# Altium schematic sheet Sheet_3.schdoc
size 305 x 189 mm
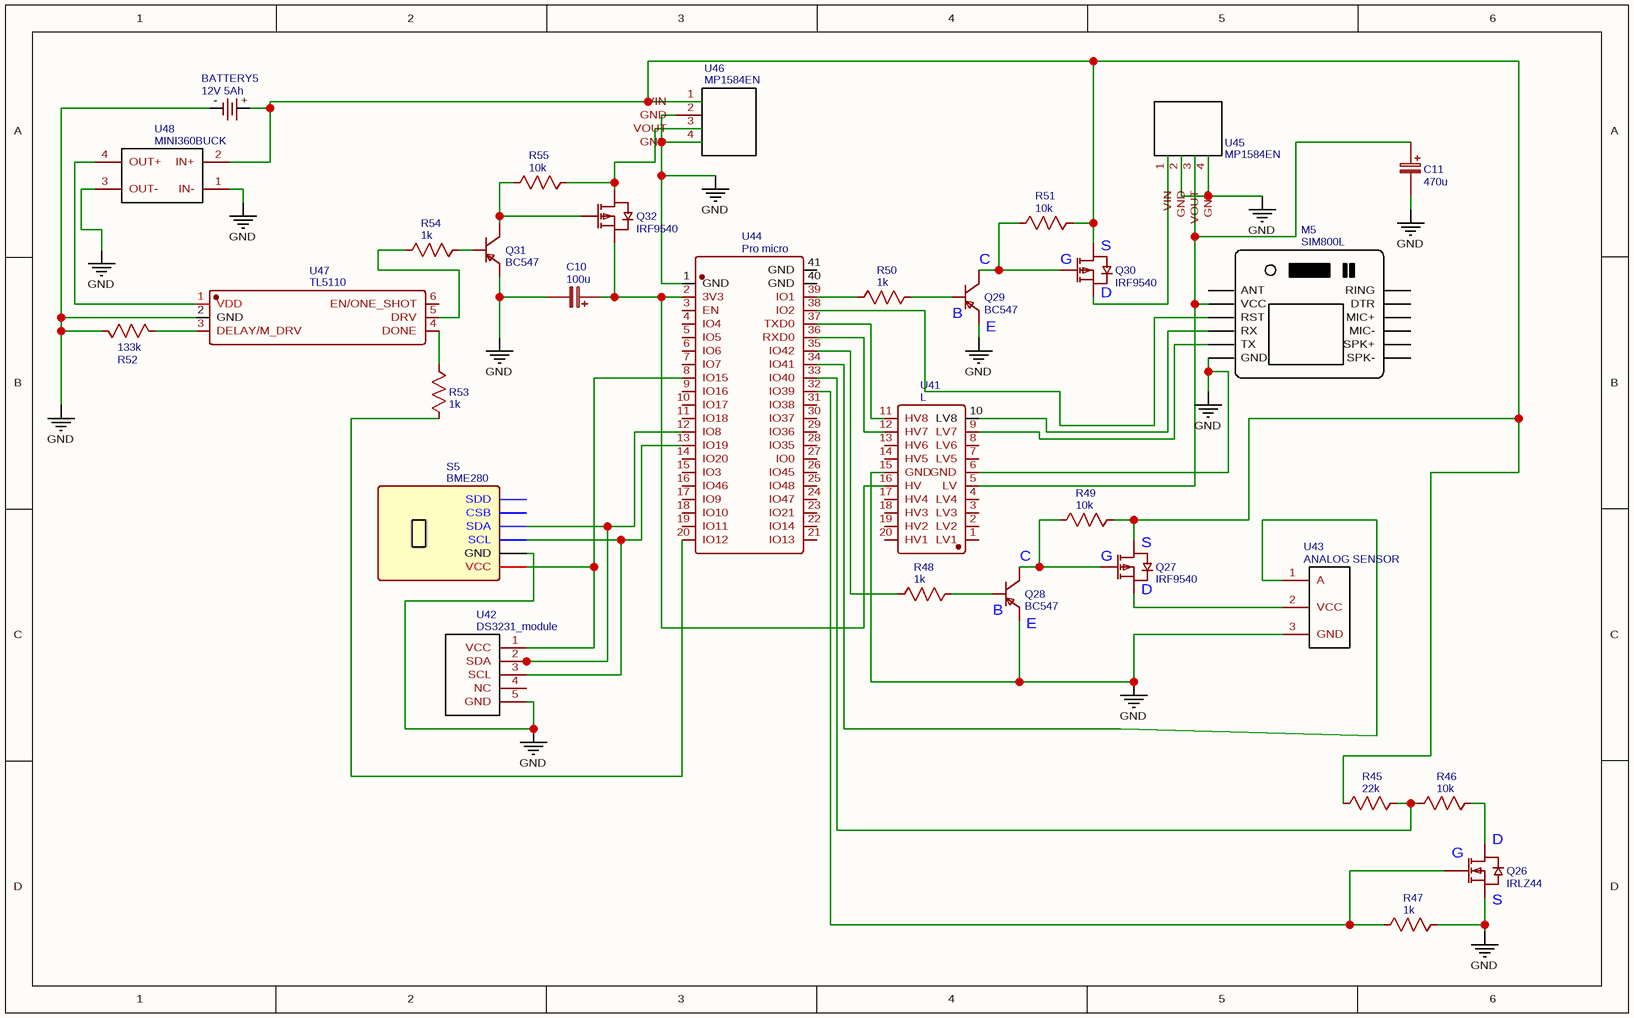
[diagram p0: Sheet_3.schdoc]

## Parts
BATTERY5  12V 5Ah  [BATTERY-SMD-MY-2032]
C10  100u  [CASE-A_3216]
C11  470u  [CASE-A_3216]
M5  SIM800L  [SIM800LMODULE_SIM800LMODULE]
Q26  IRLZ44  [TO-220-3_L10.0-W4.5-P2.54-T]
Q27  IRF9540  [TO-263-2_L10.0-W9.1-P5.08-LS15.2-BR]
Q28  BC547  [SOT-23-3_L2.9-W1.6-P1.90-LS2.8-TR-CW]
Q29  BC547  [SOT-23-3_L2.9-W1.6-P1.90-LS2.8-TR-CW]
Q30  IRF9540  [TO-263-2_L10.0-W9.1-P5.08-LS15.2-BR]
Q31  BC547  [SOT-23-3_L2.9-W1.6-P1.90-LS2.8-TR-CW]
Q32  IRF9540  [TO-263-2_L10.0-W9.1-P5.08-LS15.2-BR]
R45  22k  [R0603]
R46  10k  [R0603]
R47  1k  [R0603]
R48  1k  [R0603]
R49  10k  [R0603]
R50  1k  [R0603]
R51  10k  [R0603]
R52  133k  [R0603]
R53  1k  [R0603]
R54  1k  [R0603]
R55  10k  [R0603]
S5  BME280  [BME280]
U41  L  [MPN-TH-20_L28.0-W14.0-P2.54-BL]
U42  DS3231_module  [DS3231]
U43  ANALOG SENSOR  [ANALOG SENSOR V1]
U44  Pro micro  [WIRELM-SMD_ESP32-S3-WROOM-1U]
U45  MP1584EN  [MP1584EN]
U46  MP1584EN  [MP1584EN]
U47  TL5110  [TSOT-23-6_L2.9-W1.6-P0.95-LS2.8-BR]
U48  MINI360BUCK  [MINI360BUCK]

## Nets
GND: BATTERY5.-(BAT-) C10.2 C11.2 M5.6(GND) Q26.3(S) Q28.1(E) Q29.1(E) Q31.1(E) R47.2 R52.1 S5.2(GND) U41.6(GND) U41.15(GND) U42.5(GND) U43.3(GND) U44.1(GND) U45.2(GND) U45.4(GND) U46.4(GND) U47.2(GND) U48.1(IN-) U48.3(OUT-)
NetBATTERY5_+: BATTERY5.+(BAT+) Q27.4(D) Q30.4(D) R45.1 R49.1 R51.1 U46.1(VIN) U48.2(IN+)
NetC10_1: C10.1 Q32.3(S) U41.16(HV) U44.2(3V3)
NetC11_1: C11.1 M5.2(VCC) U41.5(LV) U45.3(VOUT)
NetM5_3: M5.3(RST) U44.38(IO2)
NetM5_4: M5.4(RX) U41.10(LV8)
NetM5_5: M5.5(TX) U41.9(LV7)
NetQ26_1: Q26.1(G) R47.1 U44.32(IO39)
NetQ26_2: Q26.2(D) R46.2
NetQ27_1: Q27.1(G) Q28.3(C) R49.2
NetQ27_3: Q27.3(S) U43.2(VCC)
NetQ28_2: Q28.2(B) R48.2
NetQ29_2: Q29.2(B) R50.2
NetQ29_3: Q29.3(C) Q30.1(G) R51.2
NetQ30_3: Q30.3(S) U45.1(VIN)
NetQ31_2: Q31.2(B) R54.1
NetQ31_3: Q31.3(C) Q32.1(G) R55.2
NetQ32_4: Q32.4(D) R55.1 U46.3(VOUT)
NetR45_2: R45.2 R46.1 U44.33(IO40)
NetR48_1: R48.1 U44.35(IO42)
NetR50_1: R50.1 U44.39(IO1)
NetR52_2: R52.2 U47.3(DELAY/M_DRV)
NetR53_1: R53.1 U47.4(DONE)
NetR53_2: R53.2 U44.20(IO12)
NetR54_2: R54.2 U47.5(DRV)
NetS5_1: S5.1(VCC) U42.1(VCC) U44.8(IO15)
NetS5_3: S5.3(SCL) U42.3(SCL) U44.13(IO19)
NetS5_4: S5.4(SDA) U42.2(SDA) U44.12(IO8)
NetU41_11: U41.11(HV8) U44.37(TXD0)
NetU41_12: U41.12(HV7) U44.36(RXD0)
NetU43_1: U43.1(A) U44.34(IO41)
NetU47_1: U47.1(VDD) U48.4(OUT+)

Not connected (* = marked no-connect by the designer): M5 1(ANT) 7(SPK-) 8(SPK+) 9(MIC-) 10(MIC+) 11(DTR) 12(RING); S5 5(CSB) 6(SDD); U41 1(LV1) 2(LV2) 3(LV3) 4(LV4) 7(LV5) 8(LV6) 13(HV6) 14(HV5) 17(HV4) 18(HV3) 19(HV2) 20(HV1); U42 4(NC); U44 3(EN) 4(IO4) 5(IO5) 6(IO6) 7(IO7) 9(IO16) 10(IO17) 11(IO18) 14(IO20) 15(IO3) 16(IO46) 17(IO9) 18(IO10) 19(IO11) 21(IO13) 22(IO14) 23(IO21) 24(IO47) 25(IO48) 26(IO45) 27(IO0) 28(IO35) 29(IO36) 30(IO37) 31(IO38) 40(GND) 41(GND); U46 2(GND); U47 6(EN/ONE_SHOT)

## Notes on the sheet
- (near Q29) C
- (near Q30) G
- (near Q30) S
- (near Q30) D
- (near Q29) B
- (near Q29) E
- (near Q28) C
- (near Q27) G
- (near Q27) S
- (near Q28) B
- (near Q28) E
- (near Q27) D
- (near Q26) G
- (near Q26) S
- (near Q26) D

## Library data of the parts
BATTERY5 = 12V 5Ah: Manufacturer: MYOUNG(美阳); Manufacturer Part: MY-2032-10; Contributor: lcsc
C10 = 100u: nameAlias: Value(F); Contributor: LCEDA_Lib
C11 = 470u: nameAlias: Value(F); Contributor: LCEDA_Lib
M5 = SIM800L: Contributor: sharad.rask
Q26 = IRLZ44: Manufacturer: Infineon(英飞凌); Manufacturer Part: IRLZ44NPBF
Q27 Q30 Q32 = IRF9540: Manufacturer: IR; Manufacturer Part: IRF5210STRLPBF; Paste Type: expand; Contributor: LCEDA_Lib
Q28 Q29 Q31 = BC547: Manufacturer: KEC; Manufacturer Part: 2N3906S-RTK/PS; Contributor: LCEDA_Lib
R45 = 22k: nameAlias: Value(Ω); Contributor: LCEDA_Lib
R46 R49 R51 R55 = 10k: nameAlias: Value(Ω); Contributor: LCEDA_Lib
R47 R48 R50 R53 R54 = 1k: nameAlias: Value(Ω); Contributor: LCEDA_Lib
R52 = 133k: nameAlias: Value(Ω); Contributor: LCEDA_Lib
U41 = L: Manufacturer: null; Manufacturer Part: Level Converter 8; Contributor: LCSC
U42 = DS3231_module: Contributor: retret
U43 = ANALOG SENSOR: Contributor: utbahR
U44 = Pro micro: Manufacturer: null; Manufacturer Part: ESP32-S3-WROOM-1U; Contributor: lcsc
U45 U46 = MP1584EN: Contributor: babeinlovexd
U47 = TL5110: Manufacturer: TI(德州仪器); Manufacturer Part: TPL5110DDCR; Contributor: lcsc; nameAlias: Value
U48 = MINI360BUCK: Contributor: Andrey Fedorov; sourceId: FRLFXR8qI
